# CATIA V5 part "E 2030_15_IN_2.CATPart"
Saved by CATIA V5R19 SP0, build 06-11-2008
Material "Plastic": density 1200 kg/m3, Young's modulus 2.2e+09 Pa, Poisson ratio 0.38, thermal expansion 6.84e-05 1/K
Bounding box of the stored display mesh (mm): x 15.1 to 30.2, y -7.54 to 7.54, z -2 to 0
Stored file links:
  G:\UTB\Kombinované\Bakalářská práce\Catia\FORMA\E 2030_15_IN_2.CATPart
  D:\Aplikace\CATIA\Nová složka\win_b64\startup\materials\Catalog.CATMaterial
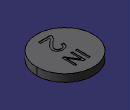
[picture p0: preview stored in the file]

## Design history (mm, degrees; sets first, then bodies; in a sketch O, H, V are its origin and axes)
Body1 "E 2030_15_IN_1-8" (main body)
  Solid1: solid without history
